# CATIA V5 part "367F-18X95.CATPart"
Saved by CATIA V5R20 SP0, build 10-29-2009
Part number: 367F-18X95
Definition: NONE
Nomenclature: 367F-18X95
Source: Unknown
Description: 367F-18X95
Bounding box of the stored display mesh (mm): x 0 to 95, y -14 to 14, z -14 to 14
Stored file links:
  C:\Users\Utente\Desktop\IO LAVORO\3D X SITO CF\X SITO\PLASTICA\3D files 367\367F-18X95.CATPart
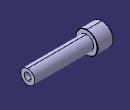
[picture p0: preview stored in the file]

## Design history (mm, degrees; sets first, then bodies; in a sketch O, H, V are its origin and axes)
Body1 "367F-18X95" (main body)
  Solid1: solid without history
